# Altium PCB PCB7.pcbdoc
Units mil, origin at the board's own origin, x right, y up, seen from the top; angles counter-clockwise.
Board outline 1129.92 x 2672.95 mil, 2 copper layers (Top Layer, Bottom Layer); 44 components, 25 nets, 183 pads, 78 vias.
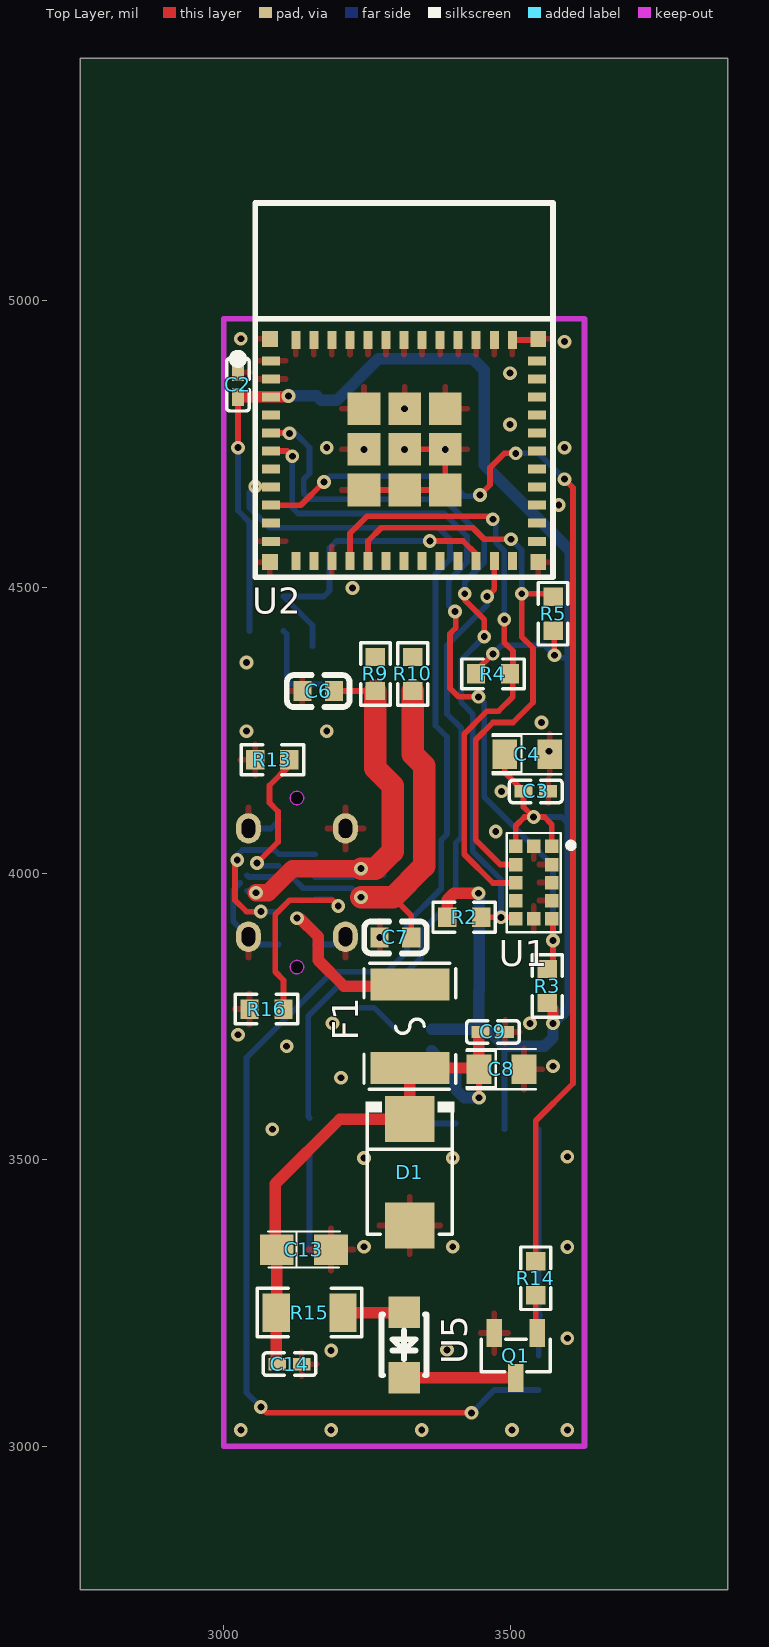
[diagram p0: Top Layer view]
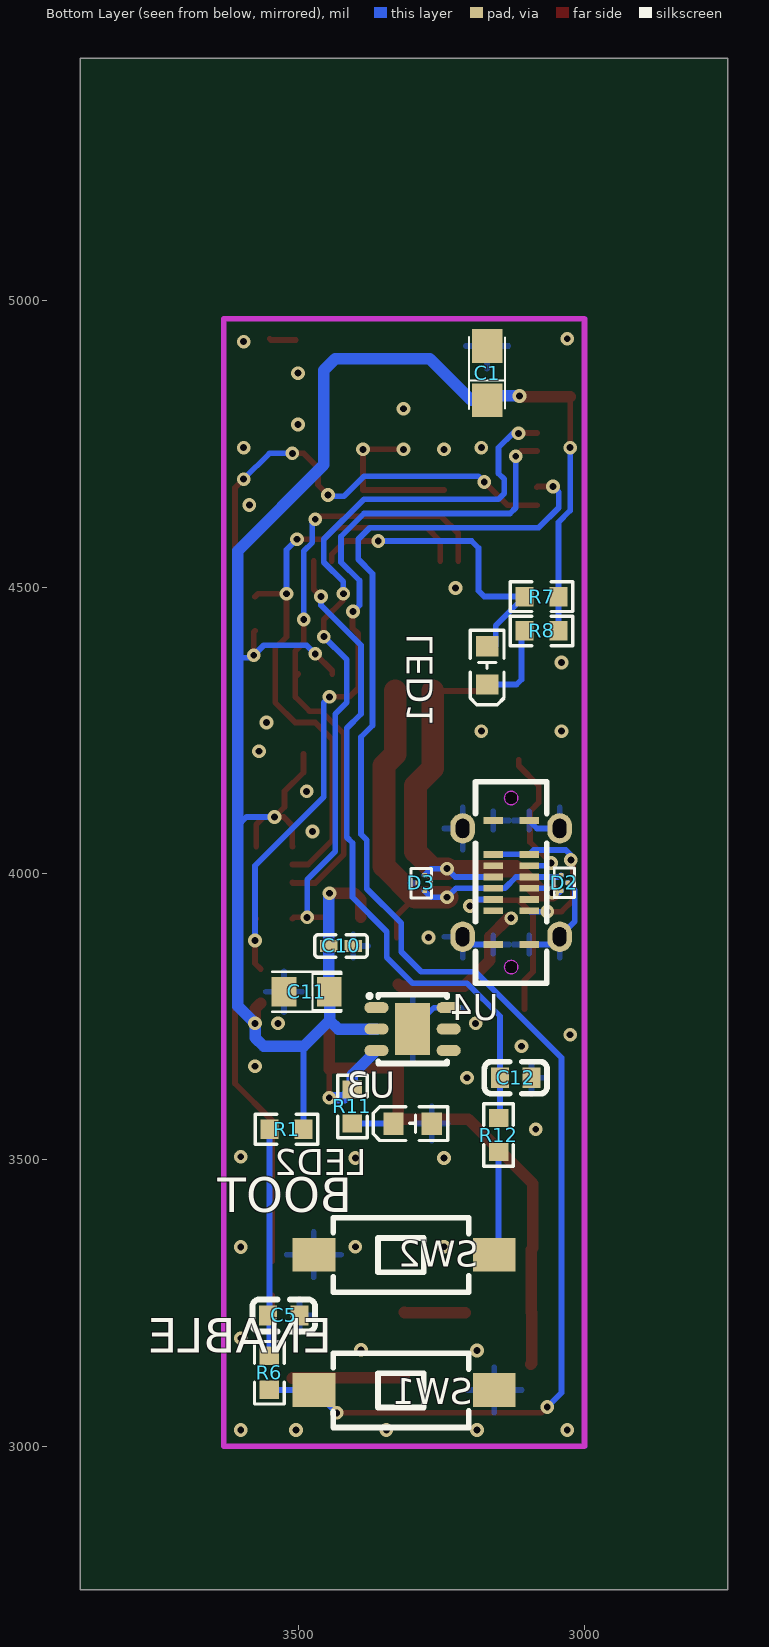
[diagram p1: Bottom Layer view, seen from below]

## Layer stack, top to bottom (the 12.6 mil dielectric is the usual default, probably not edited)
Top Layer: signal copper (thickness not stored)
Dielectric: dielectric 12.6, FR-4, Dk 4.8
Bottom Layer: signal copper (thickness not stored)

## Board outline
3879.92,2750 2750,2750 2750,5422.95 3879.92,5422.95

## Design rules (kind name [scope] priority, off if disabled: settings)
BoardOutlineClearance copperThickness1oz [All] p0: genericclearance=10 ignorepadtopadclearanceinfootprint=FALSE except(0: Arc-SplitContinuation Track-SplitContinuation SMDPad-SplitContinuation THPad-SplitContinuation Via-SplitContinuation Fill-SplitContinuation Poly-SplitContinuation Region-SplitContinuation Text-SplitContinuation; 6: Track-CutoutEdge SMDPad-CutoutEdge THPad-CutoutEdge Via-CutoutEdge Region-CutoutEdge; 11.8: Track-OutlineEdge SMDPad-OutlineEdge THPad-OutlineEdge Via-OutlineEdge Fill-OutlineEdge Region-OutlineEdge Poly-OutlineEdge Text-OutlineEdge Fill-CutoutEdge)
BoardOutlineClearance copperThickness2oz [All] p0: genericclearance=10 ignorepadtopadclearanceinfootprint=FALSE except(0: Arc-SplitContinuation Track-SplitContinuation SMDPad-SplitContinuation THPad-SplitContinuation Via-SplitContinuation Fill-SplitContinuation Poly-SplitContinuation Region-SplitContinuation Text-SplitContinuation; 6: Track-CutoutEdge SMDPad-CutoutEdge THPad-CutoutEdge Via-CutoutEdge Region-CutoutEdge; 11.8: Track-OutlineEdge SMDPad-OutlineEdge THPad-OutlineEdge Via-OutlineEdge Fill-OutlineEdge Region-OutlineEdge Poly-OutlineEdge Text-OutlineEdge Fill-CutoutEdge)
Clearance copperThickness1oz [(InNet('VDD33') OR InNet('GND') OR InNet('$3N26046') OR InNet('GPIO12_USB_DN') OR InNet('GPIO13_USB_DP') OR InNet('+5V_USB') OR InNet('$3N7934') OR InNet('$3N18951') OR InNet('$3N4848') OR InNet('$3N6215') OR InNet('$3N14553') OR InNet('$3N11377') OR InNet('$3N11381') OR InNet('GPIO2') OR InNet('GPIO3') OR InNet('I2C_SDA') OR InNet('I2C_SCL') OR InNet('ENABLE') OR InNet('$3N7054') OR InNet('$3N7060') OR InNet('$3N26307') OR InNet('$3N17638') OR InNet('GPIO4') OR InNet('$3N11357') OR InNet('$3N17354'))] p1: gap=7 ignorepadtopadclearanceinfootprint=FALSE except(4: Track-Track; 6: Track-SMDPad SMDPad-SMDPad Track-THPad SMDPad-THPad THPad-THPad Track-Via SMDPad-Via THPad-Via Via-Via SMDPad-Fill THPad-Fill Via-Fill Fill-Fill Track-Region SMDPad-Region THPad-Region Via-Region Region-Region Track-Poly SMDPad-Poly THPad-Poly Via-Poly Fill-Poly Region-Poly Poly-Poly Track-Text SMDPad-Text THPad-Text Via-Text Fill-Text Region-Text Poly-Text Text-Text; 6.9: Track-Hole SMDPad-Hole THPad-Hole Via-Hole Fill-Hole Region-Hole Poly-Hole Text-Hole Sheet-Hole; 11.8: Track-Fill Fill-Region Track-Sheet SMDPad-Sheet THPad-Sheet Via-Sheet Fill-Sheet Region-Sheet Poly-Sheet Text-Sheet)
Clearance copperThickness2oz [All] p1: gap=7 ignorepadtopadclearanceinfootprint=FALSE except(6: Track-SMDPad SMDPad-SMDPad Track-THPad SMDPad-THPad THPad-THPad Track-Via SMDPad-Via THPad-Via Via-Via SMDPad-Fill THPad-Fill Via-Fill Fill-Fill Track-Region SMDPad-Region THPad-Region Via-Region Region-Region Track-Poly SMDPad-Poly THPad-Poly Via-Poly Fill-Poly Region-Poly Poly-Poly Track-Text SMDPad-Text THPad-Text Via-Text Fill-Text Region-Text Poly-Text Text-Text; 6.9: Track-Hole SMDPad-Hole THPad-Hole Via-Hole Fill-Hole Region-Hole Poly-Hole Text-Hole Sheet-Hole; 8: Track-Track; 11.8: Track-Fill Fill-Region Track-Sheet SMDPad-Sheet THPad-Sheet Via-Sheet Fill-Sheet Region-Sheet Poly-Sheet Text-Sheet)
DiffPairsRouting differentialPair [All] p1: maxuncoupledlength=10 minlimit=5.9843 maxlimit=5.9843 mostfreqgap=5.9843 toplayer_minwidth=5 toplayer_prefwidth=10 toplayer_maxwidth=100 bottomlayer_minwidth=5 bottomlayer_prefwidth=10 bottomlayer_maxwidth=100
PasteMaskExpansion pasteMaskExpansion [All] p1: expansion=0
PlaneConnect innerPlane [All] p1: planeconnectstyle=Relief reliefexpansion=20 reliefentries=4 reliefconductorwidth=10 reliefairgap=10
PolygonConnect copperRegion [All] p1: connectstyle=Direct reliefentries=4 reliefconductorwidth=10 polygonreliefangle="90 Angle" airgapwidth=10
PolygonConnect USB_CR [All] p1: connectstyle=Direct reliefentries=4 reliefconductorwidth=10 polygonreliefangle="90 Angle" airgapwidth=10
PolygonConnect GND [All] p1: connectstyle=Relief reliefentries=4 reliefconductorwidth=10 polygonreliefangle="90 Angle" airgapwidth=10
RoutingVias viaSize [All] p1: viastyle="Through Hole" holewidth=12.0078 minholewidth=11.811 maxholewidth=248.0314 width=24.0158 minwidth=19.685 maxwidth=393.7008
SolderMaskExpansion solderMaskExpansion [All] p1: useseparateexpansions=TRUE expansion=2.0079 expansionbottom=2.0079
Width copperThickness1oz [All] p1: maxlimit=100 minlimit=5 preferedwidth=10
Width copperThickness2oz [All] p1: maxlimit=100 minlimit=8 preferedwidth=10

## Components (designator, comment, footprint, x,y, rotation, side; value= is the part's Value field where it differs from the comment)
C1 "" CASE-A_3216 3170,4873.5 r90 bottom
C2 "" C0402 3025,4853.5 r270 top locked
C3 "" C0402 3545,4143.5 r0 top
C4 "" CAP-SMD_L2.0-W1.3-FD 3530,4208.5 r0 top
C5 "" C0603 3525,3228.5 r180 bottom
C6 "" C0603 3165,4318.5 r180 top
C7 "" C0603 3300,3888.5 r180 top
C8 "" CAP-SMD_L2.0-W1.3-FD 3485,3658.5 r0 top
C9 "" C0402 3470,3723.5 r0 top
C10 "" C0402 3425,3873.5 r180 bottom
C11 "" CAP-SMD_L2.0-W1.3-FD 3485,3793.5 r0 bottom
C12 "" C0603 3120,3643.5 r180 bottom
C13 "" CASE-A_3216 3140,3343.5 r0 top
C14 "" C0402 3115,3143.5 r180 top
D1 "" SMB_L4.6-W3.6-LS5.3-RD 3325,3478.5 r270 top
D2 "" X2SON-3_L1.0-W0.6-L 3035,3983.5 r0 bottom
D3 "" X2SON-3_L1.0-W0.6-L 3285,3983.5 r180 bottom
F1 "" F1812 3325,3733.5 r90 top
LED1 "" LED0603-FD 3170,4363.5 r270 bottom
LED2 "" LED0603-FD 3300,3563.5 r0 bottom
Q1 "" SOT-23-3_L2.9-W1.3-P1.90-LS2.4-BR 3510,3158.5 r90 top
R1 "" R0603 3520,3553.5 r180 bottom
R2 "" R0603 3420,3923.5 r180 top
R3 "" R0603 3565,3803.5 r270 top
R4 "" R0603 3470,4348.5 r180 top
R5 "" R0603 3575,4453.5 r270 top
R6 "" R0603 3550,3128.5 r270 bottom
R7 "" R0603 3075,4483.5 r180 bottom
R8 "" R0603 3075,4423.5 r180 bottom
R9 "" R0603 3265,4348.5 r90 top
R10 "" R0603 3330,4348.5 r90 top
R11 "" R0603 3405,3593.5 r270 bottom
R12 "" R0603 3150,3543.5 r90 bottom
R13 "" R0603 3085,4198.5 r0 top
R14 "" R0603 3545,3293.5 r270 top
R15 "" R1206 3150,3233.5 r0 top
R16 "" R0603 3075,3763.5 r0 top
SW1 "" SW-SMD_L6.0-W3.3-LS8.0 3314.96,3098.43 r180 bottom locked
SW2 "" SW-SMD_L6.0-W3.3-LS8.0 3314.96,3334.65 r180 bottom locked
U1 "" OPTO-SMD_12P_VL53L3CXV0DH 3541.34,3984.25 r90 top
U2 "" WIFIM-SMD_61P-L16.6-W13.2-P0.80-ESP32-C6-MINI-1-N4 3314.96,4738.5 r0 top locked
U3 "" DFN-6_L3.0-W3.0-P0.95-BL-EP-1 3300,3728.5 r270 bottom
U4 "" TYPE-C-SMD_USB4120-03-C 3127.95,3984.25 r90 bottom locked
U5 "" LED-SMD_L3.0-W2.0-R-RD 3314.96,3177.17 r90 top locked

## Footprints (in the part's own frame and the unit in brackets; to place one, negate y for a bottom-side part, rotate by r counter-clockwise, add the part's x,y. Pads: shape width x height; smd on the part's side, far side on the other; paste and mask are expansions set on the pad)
C0402 [mm]
  rect 0.79x0.54 smd: 1(-0.545,0) 2(0.545,0)
  silkscreen extent -1.17,-0.5 1.17,0.5
C0603 [mm]
  rect 0.8x0.9 smd: 1(-0.7,0) 2(0.7,0)
  silkscreen extent -1.39,-0.71 1.39,0.71
CAP-SMD_L2.0-W1.3-FD [mm]
  rect 1.1x1.3 smd: 1(-1,0) 2(1,0)
  silkscreen extent -1.57,-0.89 1.52,0.89
CASE-A_3216 [mil]
  rect 59.05x53.5 smd: 1(-47.24,0) 2(47.24,0)
  silkscreen extent -63,-32 63,32
DFN-6_L3.0-W3.0-P0.95-BL-EP-1 [mm]
  oval 0.49x1.07 smd: 1(-0.95,-1.6) 2(0,-1.6) 3(0.95,-1.6) 4(0.95,1.6) 5(0,1.6) 6(-0.95,1.6)
  rect 2.3x1.55 smd: 7(0,0)
  silkscreen extent -1.56,-2 1.52,1.52
F1812 [mil]
  rect 55.38x137.76 smd: 1(-72.97,0) 2(72.97,0)
  silkscreen extent -110,-80 110,80
LED0603-FD [mm]
  rect 0.9x1 smd: 1(-0.85,0) 2(0.85,0)
  silkscreen extent -1.55,-0.75 1.75,0.75
LED-SMD_L3.0-W2.0-R-RD [mm]
  rect 1.4x1.4 smd: 1(1.45,0) 2(-1.45,0)
  silkscreen extent -1.35,-1 1.35,1
OPTO-SMD_12P_VL53L3CXV0DH [mm]
  rect 0.6x0.6 smd: 1(1.6,-0.8) 2(0.8,-0.8) 3(0,-0.8) 4(-0.8,-0.8) 5(-1.6,-0.8) 6(-1.6,0) 7(-1.6,0.8) 8(-0.8,0.8) 9(0,0.8) 10(0.8,0.8) 11(1.6,0.8) 12(1.6,0)
  silkscreen extent -2.2,-1.78 2.2,1.2
R0603 [mil]
  rect 31.75x34.02 smd: 1(-29.66,0) 2(29.66,0)
  silkscreen extent -55,-26 55,26
R1206 [mil]
  rect 47.54x66.97 smd: 1(-58.22,0) 2(58.22,0)
  silkscreen extent -91,-42 91,42
SMB_L4.6-W3.6-LS5.3-RD [mil]
  rect 80.61x86.31 smd: 1(-92.94,0) 2(92.94,0)
  silkscreen extent -123,-77 108,77
SOT-23-3_L2.9-W1.3-P1.90-LS2.4-BR [mm]
  rect 1.25x0.7 smd: 1(1,-0.95) 2(1,0.95) 3(-1,0)
  silkscreen extent -0.73,-1.53 0.73,1.53
SW-SMD_L6.0-W3.3-LS8.0 [mm]
  rect 1.9x1.5 smd: 1(-4,0) 2(4,0)
  silkscreen extent -3.14,-1.67 2.86,1.63
TYPE-C-SMD_USB4120-03-C [mm]
  oval 1.35x1.1 hole 0.6 slot 0.85 at 0 deg: 0(-2.4,-2.15) 0(-2.4,2.15) 0(2.4,-2.15) 0(2.4,2.15)
  rect 0.3x0.87 smd: A1(-2.75,0.8) A4(-1.25,0.8) A5(-0.75,0.8) A6(-0.25,0.8) A7(0.25,0.8) A8(0.75,0.8) A9(1.25,0.8) A12(2.75,0.8) B1(2.75,-0.8) B4(1.25,-0.8) B5(0.75,-0.8) B6(0.25,-0.8) B7(-0.25,-0.8) B8(-0.75,-0.8) B9(-1.25,-0.8) B12(-2.75,-0.8)
  Board Outline Layer circle w0.005: c-3.75,0 r0.3
  Board Outline Layer circle w0.005: c3.75,0 r0.3
  Board Outline Layer region: -3.75,0.3 -3.88,0.27 -3.985,0.187 -4.043,0.067 -4.043,-0.067 -3.985,-0.187 -3.88,-0.27 -3.75,-0.3 -3.75,-0.3 -3.62,-0.27 -3.516,-0.187 -3.458,-0.067 -3.458,0.067 -3.516,0.187 -3.62,0.27 -3.75,0.3
  Board Outline Layer region: 3.75,0.3 3.62,0.27 3.516,0.187 3.458,0.067 3.458,-0.067 3.516,-0.187 3.62,-0.27 3.75,-0.3 3.75,-0.3 3.88,-0.27 3.985,-0.187 4.043,-0.067 4.043,0.067 3.985,0.187 3.88,0.27 3.75,0.3
  Multi-Layer board cut-out: -3.75,0.3 -3.88,0.27 -3.985,0.187 -4.043,0.067 -4.043,-0.067 -3.985,-0.187 -3.88,-0.27 -3.75,-0.3 -3.75,-0.3 -3.62,-0.27 -3.516,-0.187 -3.458,-0.067 -3.458,0.067 -3.516,0.187 -3.62,0.27 -3.75,0.3
  Multi-Layer board cut-out: 3.75,0.3 3.62,0.27 3.516,0.187 3.458,0.067 3.458,-0.067 3.516,-0.187 3.62,-0.27 3.75,-0.3 3.75,-0.3 3.88,-0.27 3.985,-0.187 4.043,-0.067 4.043,0.067 3.985,0.187 3.88,0.27 3.75,0.3
  silkscreen extent -4.47,-1.58 4.47,1.58
WIFIM-SMD_61P-L16.6-W13.2-P0.80-ESP32-C6-MINI-1-N4 [mm]
  rect 0.8x0.4 smd: 1(-5.9,3.975) 2(-5.9,3.175) 3(-5.9,2.375) 4(-5.9,1.575) 5(-5.9,0.775) 6(-5.9,-0.025) 7(-5.9,-0.825) 8(-5.9,-1.625) 9(-5.9,-2.425) 10(-5.9,-3.225) 11(-5.9,-4.025) 25(5.9,-4.025) 26(5.9,-3.225) 27(5.9,-2.425) 28(5.9,-1.625) 29(5.9,-0.825) 30(5.9,-0.025) 31(5.9,0.775) 32(5.9,1.575) 33(5.9,2.375) 34(5.9,3.175) 35(5.9,3.975)
  rect 0.4x0.8 smd: 12(-4.8,-4.9) 13(-4,-4.9) 14(-3.2,-4.9) 15(-2.4,-4.9) 16(-1.6,-4.9) 17(-0.8,-4.9) 18(0,-4.9) 19(0.8,-4.9) 20(1.6,-4.9) 21(2.4,-4.9) 22(3.2,-4.9) 23(4,-4.9) 24(4.8,-4.9) 36(4.8,4.9) 37(4,4.9) 38(3.2,4.9) 39(2.4,4.9) 40(1.6,4.9) 41(0.8,4.9) 42(0,4.9) 43(-0.8,4.9) 44(-1.6,4.9) 45(-2.4,4.9) 46(-3.2,4.9) 47(-4,4.9) 48(-4.8,4.9)
  rect 1.45x1.45 smd: 49(-1.775,-1.75) 49(-1.775,0.05) 49(-1.775,1.85) 49(0.025,-1.75) 49(0.025,0.05) 49(0.025,1.85) 49(1.825,-1.75) 49(1.825,0.05) 49(1.825,1.85)
  rect 0.7x0.7 smd: 50(5.95,4.95) 51(5.95,-4.95) 52(-5.95,-4.95) 53(-5.95,4.95)
  silkscreen extent -7.57,-5.62 6.6,10.98
X2SON-3_L1.0-W0.6-L [mm]
  rect 0.2x0.2 smd: 1(-0.15,0) 2(0.15,-0.34) 3(0.15,0.34)
  silkscreen extent -0.45,-0.66 0.45,0.64

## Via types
v1: diameter 24.02, hole 12.01, Top Layer to Bottom Layer, 78 vias

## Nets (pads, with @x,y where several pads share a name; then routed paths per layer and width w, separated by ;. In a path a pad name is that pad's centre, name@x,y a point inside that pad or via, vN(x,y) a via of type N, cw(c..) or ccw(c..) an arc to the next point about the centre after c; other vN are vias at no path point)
$3N4848: LED1.1 R7.1 U2.22 | length 549.3
  Top Layer w10: v1(3360,4580.51) 3417.99,4580.51 3440.94,4557.56 U2.22
  Bottom Layer w10: LED1.1@3155,4396.97 3155,4433.16 R7.1 3175,4483.5 3185,4493.5 3185,4568.5 3197.01,4580.51 v1(3360,4580.51)
$3N6215: LED1.2 R8.1 | length 150.7
  Bottom Layer w10: R8.1 3110,4418.16 3110,4338.5 3118.47,4330.04 LED1.2
$3N7054: R9.2 U2.17
$3N7060: R10.2 U2.18
$3N7934: C12.1 R12.2 U2.23 | length 1184.4
  Top Layer w10: v1(3460,4483.5) 3472.44,4495.95 U2.23
  Bottom Layer w10: R12.2 3147.56,3575.6 C12.1 3147.56,3751.06 3205,3808.5 3300,3808.5 3345,3853.5 3345,3898.5 3405,3958.5 3405,4053.5 3415,4063.5 3415,4253.5 3390,4278.5 3390,4398.5 3460,4468.5 v1(3460,4483.5)
$3N11357: R15.2 U5.1 | length 107.1
  Top Layer w20: R15.2 3314.21,3233.5 U5.1
$3N11377: Q1.1 R14.2 | length 67
  Top Layer w10: R14.2 3545,3200.27 Q1.1
$3N11381: Q1.3 U5.2 | length 195.4
  Top Layer w20: U5.2 3509.06,3120.08 Q1.3
$3N14553: LED2.2 R11.2 | length 71.7
  Bottom Layer w10: LED2.2 3404.66,3563.5 R11.2
$3N17354: R16.2 U4.A5 | length 340.8
  Top Layer w10: R16.2 3104.66,3813.84 3090,3828.5 3090,3928.5 3115,3953.5 3190,3953.5 v1(3200,3943.5)
  Bottom Layer w10: U4.A5 3188.78,3954.72 v1(3200,3943.5)
$3N17638: R13.2 U4.B5 | length 256
  Top Layer w10: v1(3058.36,4018.19) 3095,4054.83 3095,4108.5 3080,4123.5 3080,4153.5 3114.66,4188.16 R13.2
  Bottom Layer w10: v1(3058.36,4018.19) 3062.77,4013.78 U4.B5
$3N18951: F1.2 U4.A4 U4.A9 U4.B4 U4.B9 | length 580
  Top Layer w10: v1(3023.82,4023.5) 3020,4019.68 3020,3953.5 3040,3933.5 v1(3065,3933.5)
  Top Layer w20: v1(3127.95,3922.1) 3132.95,3922.1 3165,3890.05 3165,3848.5 3210,3803.5 3322.03,3803.5 F1.2
  Bottom Layer w10: v1(3023.82,4023.5) 3023.82,4032.32 3032.68,4041.18 3088.74,4041.18 U4.B4 U4.A9 ; v1(3065,3933.5) 3094.92,3933.5 U4.B9
$3N26046: C5.1 R1.1 R6.1 | length 397.6
  Bottom Layer w10: R1.1 3549.66,3231.4 C5.1 3550,3225.94 R6.1
$3N26307: R12.1 SW2.2 | length 182.3
  Bottom Layer w10: R12.1 3150,3342.13 SW2.2
+5V_USB: C8.1 C9.1 C13.1 C14.2 D1.1 F1.1 R11.1 R15.1 U3.3 | length 1057.9
  Top Layer w10: v1(3445.63,3608.5) C8.1
  Top Layer w20: C14.2 3091.78,3145.26 R15.1 3092.76,3234.48 C13.1 3090,3346.26 3090,3458.5 3202.94,3571.44 D1.1 F1.1 3443.6,3660.53 C8.1 3445.63,3720.59 C9.1
  Bottom Layer w20: U3.3 3405,3649.1 R11.1 3419.66,3608.5 v1(3445.63,3608.5)
ENABLE: R6.2 SW1.1 U2.8 | length 2692.6
  Top Layer w10: v1(3055,4675.61) 3081.58,4675.61 U2.8 ; v1(3065,3068.5) 3075,3058.5 v1(3432.52,3058.5)
  Bottom Layer w10: v1(3055,4675.61) 3045,4665.61 3045,4638.5 3080,4603.5 3375,4603.5 3395,4583.5 3395,4548.5 3370,4523.5 3370,4258.5 3390,4238.5 3390,4068.5 3380,4058.5 3380,3973.5 3320,3913.5 3320,3863.5 3285,3828.5 3190,3828.5 3040,3678.5 3040,3093.5 v1(3065,3068.5) ; v1(3432.52,3058.5) SW1.1 3549.58,3098.43 R6.2
GND: C1.2 C2.1 C3.2 C4.2 C5.2 C6.2 C7.2 C8.2 C9.2 C10.2 C11.2 C12.2 C13.2 C14.1 D1.2 D2.1 D3.1 LED2.1 Q1.2 R13.1 R16.1 SW1.2 SW2.1 U1.2 U1.3 U1.4 U1.6 U1.12 U2.1 U2.2 U2.11 U2.14 U2.36 U2.37 U2.38 U2.39 U2.40 U2.41 U2.42 U2.43 U2.44 U2.45 U2.46 U2.47 U2.48 U2.49 U2.50 U2.51 U2.52 U2.53 U3.6 U3.7 U4.0 U4.A1 U4.A12 U4.B1 U4.B12 | length 694.4
  Top Layer w10: U2.49@3245.07,4669.61 3315.94,4669.61 3386.8,4669.61 v1(3386.8,4740.47) v1(3315.94,4740.47) ; U2.36 3547.24,4931.41 U2.50
  Bottom Layer w10: D2.1 3016.81,3971.22 3016.81,3916.26 3043.31,3889.76 3057.09,3875.98 U4.B12 ; U4.0@3043.31,4078.74 3082.68,4078.74 U4.B1 ; U4.A1 3198.82,3875.98 U4.0@3212.6,3889.76 ; U3.6 3262.61,3765.9 U3.7
  other v1: 3030,3028.5 3187.7,3028.5 3345.92,3028.5 3503.42,3028.5 3600,3028.5 3187.7,3167.51 3390,3168.5 3600,3188.69 3600,3347.84 3245,3348.5 3400,3348.5 3245,3503.5 3400,3503.5 3600,3505.6 3085,3553.5 3205,3643.5 3575,3663.5 3110,3698.5 3025,3718.5 3190,3738.5 3535,3738.5 3272.44,3888.5 3475,4073.5 3485,4143.5 3567.99,4213.5 3040,4248.5 3180,4248.5 3555,4263.5 3040,4368.5 3225,4498.5 3585,4643.5 3245.07,4740.47 3180,4743.5 3595,4743.5 3500,4784 3315.94,4811.34 3500,4873.5 3595,4928.5 3030,4933.5
GPIO2: R2.1 U1.7 U2.5 | length 1304.7
  Top Layer w10: U2.5 3114.49,4769.01 v1(3115,4768.5) ; v1(3420.92,4488.5) 3420.92,4477.58 3455,4443.5 v1(3455,4413.5) ; R2.1 v1(3484.07,3923.5) 3507.6,3923.5 U1.7
  Bottom Layer w10: v1(3115,4768.5) 3125,4768.5 3150,4743.5 3150,4698.5 3140,4688.5 3140,4663.5 3150,4653.5 3385,4653.5 3455,4583.5 3455,4543.5 3420.92,4509.43 v1(3420.92,4488.5) ; v1(3455,4413.5) 3415,4373.5 3415,4298.5 3435,4278.5 3435,4038.5 3484.07,3989.44 v1(3484.07,3923.5)
GPIO3: R3.1 U1.5 U2.6 | length 1373
  Top Layer w10: U2.6 3110.98,4737.52 v1(3120,4728.5) ; v1(3403.96,4457.47) 3405,4456.43 3405,4428.5 3395,4418.5 3395,4323.5 3410,4308.5 v1(3445,4308.5) ; R3.1 3575,3843.16 v1(3575,3882.93) 3575,3919.1 U1.5
  Bottom Layer w10: v1(3120,4728.5) 3120,4638.5 3130,4628.5 3385,4628.5 3425,4588.5 3425,4543.5 3392.93,4511.43 3392.93,4468.5 v1(3403.96,4457.47) ; v1(3445,4308.5) 3455,4298.5 3455,4133.5 3575,4013.5 v1(3575,3882.93)
GPIO4: R14.1 U2.9 | length 2013.5
  Top Layer w10: U2.9 3134.53,4643.03 v1(3175,4683.5) ; v1(3447.5,4661) 3465,4678.5 3465,4708.5 3490,4733.5 v1(3510,4733.5) ; R14.1 3545,3568.5 3610,3633.5 3610,4673.5 v1(3595,4688.5)
  Bottom Layer w10: v1(3175,4683.5) 3185,4693.5 3385,4693.5 3420,4658.5 3445,4658.5 v1(3447.5,4661) ; v1(3510,4733.5) 3550,4733.5 v1(3595,4688.5)
GPIO12_USB_DN: C6.1 D2.3 D3.3 R9.1 U4.A7 U4.B7 | length 824.6
  Top Layer w10: C6.1 3264.66,4318.5 R9.1
  Top Layer w30: v1(3056.38,3966.5) 3077.99,3966.5 3120,4008.5 v1(3240,4008.5)
  Top Layer w39.37: v1(3240,4008.5) 3265,4008.5 3295,4038.5 3295,4153.5 3265,4183.5 R9.1
  Bottom Layer w10: D2.3 3044.53,3966.5 v1(3056.38,3966.5) 3064.29,3974.41 U4.B7 ; U4.A7 3225.59,3994.09 v1(3240,4008.5) 3267.48,4008.5 D3.3
GPIO13_USB_DP: C7.1 D2.2 D3.2 R10.1 U4.A6 U4.B6 | length 788.9
  Top Layer w10: 3295.68,3958.5 3327.56,3926.62 C7.1
  Top Layer w39.37: v1(3240,3958.5) 3295.68,3958.5 3350,4012.83 3350,4188.5 3330,4208.5 R10.1
  Bottom Layer w10: D2.2 3043.7,3994.09 U4.B6 3119.41,3994.09 3139.09,3974.41 U4.A6 3224.09,3974.41 v1(3240,3958.5) 3267.48,3958.5 D3.2
I2C_SCL: R5.1 U1.10 U2.16 | length 1049.8
  Top Layer w10: U2.16 3251.96,4580.47 3275,4603.5 3435,4603.5 3455,4583.5 v1(3501.88,4583.5) ; U1.10 3482.76,4015.74 3440,4058.5 3440,4233.5 3470,4263.5 3505,4263.5 3540,4298.5 3540,4393.5 3520.34,4413.16 v1(3520.34,4488.5) 3569.66,4488.5 R5.1
  Bottom Layer w10: v1(3501.88,4583.5) 3520,4565.38 3520,4533.5 3520.34,4533.16 v1(3520.34,4488.5)
I2C_SDA: R4.1 U1.9 U2.15 | length 1076.6
  Top Layer w10: U2.15 3220.47,4593.98 3250,4623.5 3465,4623.5 v1(3470,4618.5) ; v1(3490,4443.5) 3490,4403.5 3505,4388.5 3505,4343.84 R4.1@3504.66,4343.5 ; R4.1 R4.1@3504.66,4343.5 ; U1.9 3509.1,3983.5 3470,3983.5 3420,4033.5 3420,4243.5 3460,4283.5 3480,4283.5 3504.66,4308.16 R4.1@3504.66,4343.5
  Bottom Layer w10: v1(3470,4618.5) 3475,4613.5 3475,4577.86 3490,4562.86 v1(3490,4443.5)
VDD33: C1.1 C2.2 C3.1 C4.1 C10.1 C11.1 R1.2 R2.2 R3.2 R4.2 R5.2 R7.2 R8.2 U1.1 U1.11 U2.3 U3.2 | length 3459.5
  Top Layer w10: v1(3025,4743.5) C2.2 ; R4.2 3440.34,4353.84 v1(3470,4383.5) ; C4.1 3490.63,4176.41 C3.1 3523.54,4116.24 v1(3541.27,4098.5) ; U1.11 3510,4047.4 3510,4083.5 3525,4098.5 v1(3541.27,4098.5) ; U1.1 3572.83,4085.67 3560,4098.5 v1(3541.27,4098.5) ; R5.2 3577.39,4421.45 v1(3577.39,4381.11)
  Top Layer w20: C2.2 U2.3@3082.63,4832.04 ; U2.3 3111.46,4832 v1(3113.28,4833.82) ; R2.2 3390.34,3954.2 3401.72,3965.57 v1(3445,3965.57) ; R3.2 3575,3763.84 v1(3575,3738.5)
  Bottom Layer w10: v1(3025,4743.5) 3025,4633.5 3045.34,4613.16 R7.2 R8.2 ; v1(3470,4383.5) 3485,4398.5 3560,4398.5 v1(3577.39,4381.11) 3581.78,4376.72 3605,4376.72 ; R1.2 3490.34,3698.16 ; v1(3541.27,4098.5) 3590,4098.5 3605,4083.5
  Bottom Layer w20: v1(3113.28,4833.82) 3162.44,4833.82 C1.1 3197.76,4826.26 3270,4898.5 3435,4898.5 3455,4878.5 3455,4713.5 3605,4563.5 3605,4376.72 3605,4083.5 3605,3768.5 v1(3575,3738.5) 3575,3713.5 3559.66,3698.16 3490.34,3698.16 3445,3743.5 ; U3.2 3430,3728.5 3445,3743.5 ; v1(3445,3965.57) 3446.46,3964.11 C10.1 C11.1@3446.46,3794.33 ; C11.1 3445,3792.87 3445,3743.5
pads on no net: U1.8 U2.4 U2.7 U2.10 U2.12 U2.13 U2.19 U2.20 U2.21 U2.24 U2.25 U2.26 U2.27 U2.28 U2.29 U2.30 U2.31 U2.32 U2.33 U2.34 U2.35 U3.1 U3.4 U3.5 U4.A8 U4.B8

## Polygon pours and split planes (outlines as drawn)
$3N7060 on Top Layer (solid, remove dead copper, pour order 0): 3315,4358.5 3310,4363.5 3310,4473.5 3305,4478.5 3305,4563.5 3310,4568.5 3320,4568.5 3325,4563.5 3325,4503.5 3350,4478.5 3350,4363.5 3345,4358.5
$3N18951 on Bottom Layer (solid, remove dead copper, pour order 6): 3080,3943.5 3075,3938.5 3075,3928.5 3080,3923.5 3115,3923.5 3115,3908.5 3120,3903.5 3140,3903.5 3145,3908.5 3145,3923.5 3175,3923.5 3180,3928.5 3180,3938.5 3175,3943.5
GND on Bottom Layer (solid, remove dead copper, pour order 8): 3010,4958.5 3620,4958.5 3620,3008.5 3010,3008.5
$3N7054 on Top Layer (solid, remove dead copper, pour order 2): 3280,4358.5 3285,4363.5 3285,4468.5 3295,4478.5 3295,4563.5 3290,4568.5 3280,4568.5 3275,4563.5 3275,4503.5 3245,4473.5 3245,4363.5 3250,4358.5
GND on Top Layer (solid, remove dead copper, pour order 4): 3010,4958.5 3620,4958.5 3620,3008.5 3010,3008.5

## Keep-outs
Board Outline Layer:
  lines w10: 3000,3000 3629.92,3000 3629.92,4968.5 3000,4968.5 3000,3000

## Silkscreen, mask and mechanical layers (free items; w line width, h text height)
Bottom Silkscreen Layer:
  text "BOOT" at 3405,3408.5 h60
  text "ENABLE" at 3440,3163.5 h60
